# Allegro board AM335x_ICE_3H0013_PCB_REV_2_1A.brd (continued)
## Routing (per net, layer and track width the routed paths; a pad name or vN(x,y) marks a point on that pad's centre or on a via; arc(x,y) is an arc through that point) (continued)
PRUETH0_TXD2: length 45.5
  TOP w0.121: v1(60.93,74.53) 60.93,74.81 60.41,75.32 U3.5 ; v1(44.17,49.25) U14.R4 ; U37.12 59.3,60.97 v1(59.69,60.58)
  LYR3 w0.127: v1(59.69,60.58) 59.18,60.07 58.21,60.07 57.78,60.49 57.78,61.53 59.94,63.68 59.94,67.65 61.39,69.1 61.39,74.06 v1(60.93,74.53)
  BOTTOM w0.121: v1(44.17,49.25) 44.56,49.64 45.11,49.64 46.89,51.41 46.89,52.51 48.76,54.38 51.96,54.38 52.09,54.24 53.95,54.24 54.06,54.14 56.17,54.14 57.3,55.27 57.3,58.19 v1(59.69,60.58)
PRUETH0_TXD3: length 45.9
  TOP w0.121: v1(58.29,60.58) 58.29,60.96 58,61.25 U37.14 ; U3.6 v1(60.45,75.82) ; v1(44.97,49.25) U14.R3
  LYR3 w0.127: v1(58.29,60.58) 61.94,64.22 61.94,74.44 60.56,75.82 v1(60.45,75.82)
  BOTTOM w0.121: v1(44.97,49.25) 45.56,49.25 45.85,49.54 45.85,50.06 47.82,52.04 47.82,52.58 48.07,52.83 48.39,52.83 48.7,53.15 50.35,53.15 51.22,54.01 51.81,54.01 52.02,53.8 53.44,53.8 53.58,53.65 56.19,53.65 57.66,55.12 57.66,56.26 58.93,57.53 58.93,58.67 60.11,59.85 60.11,60.75 59.86,61 58.71,61 v1(58.29,60.58)
PRUETH0_TXEN: length 89.3
  TOP w0.121: v1(49.58,53.63) 49.58,52.91 48.24,51.57 48.24,51.23 46.2,49.19 45.63,49.19 45.37,48.93 U14.R2 ; v1(56.13,60.2) 56.7,60.76 U37.16 ; v1(33.77,43.65) U14.J16 ; v1(63.28,73.63) 61.32,73.63 61.05,73.36 60.56,73.36 60.1,73.82 U3.2
  LYR3 w0.127: v1(33.77,43.65) 33.34,44.08 28.41,44.08 26.47,46.02 26.47,50.5 28,52.03 29.32,52.03 31.15,53.86 31.91,53.86 31.93,53.85 v1(32.14,53.85)
  LYR4 w0.127: v1(32.14,53.85) 32.78,53.2 32.78,53.08 33.97,51.89 43.51,51.89 45.73,54.11 49.1,54.11 v1(49.58,53.63) 49.62,53.67 50.32,53.67 52.4,55.75 53.62,55.75 55.52,53.85 57.7,53.85 57.95,54.1 57.95,56.6 57.02,57.53 57.02,59.31 v1(56.13,60.2) ; v1(62.1,63.75) 62.1,64.27 61.96,64.41 61.96,64.9 63.11,66.05 63.11,70.64 63.72,71.25 63.72,73.19 v1(63.28,73.63)
  BOTTOM w0.121: v1(62.1,63.75) 60.56,62.21 57.13,62.21 TP32.1 56.13,61.21 v1(56.13,60.2)
PRUETH1_ACTLED: length 36.4
  TOP w0.121: U2.26 v1(33.31,78.32)
  LYR3 w0.127: v1(33.31,78.32) 34.29,79.3 34.29,82.93 32.58,84.64 32.58,91.32 36.36,95.09 36.36,95.11 37.57,96.32 37.57,100.82 37.85,101.09 39.67,101.09 v1(39.69,101.1)
  BOTTOM w0.121: R97.1 v1(39.69,101.1) 40.38,101.8 J1.12
PRUETH1_COL: length 23.5
  TOP w0.121: U7.1 43.42,67.32 43.18,67.56 42.75,67.56 v1(42.65,67.46) ; U2.42 38.49,69.35 R27.1 38.35,69.47 v1(37.72,69.47) ; U9.11 v1(29.98,63.25)
  LYR3 w0.127: v1(37.72,69.47) 37.72,69.15 32.8,64.23 30.97,64.23 v1(29.98,63.25)
  BOTTOM w0.121: v1(37.72,69.47) 38.35,68.83 38.35,67.45 38.36,67.45 38.36,67.36 38.79,66.93 40.54,66.93 41.07,67.46 v1(42.65,67.46)
PRUETH1_INTN: length 3
  TOP w0.121: R18.1 44.45,76.32 U2.7
PRUETH1_JTCK: length 3.1
  TOP w0.121: U2.8 45.73,76.82 TP16.1
PRUETH1_JTDI: length 6.8
  TOP w0.121: TP8.1 46.93,81.47 45.27,81.47 44.83,81.03 44.83,79.76 43.9,78.82 U2.12
PRUETH1_JTDO: length 3.3
  TOP w0.121: TP14.1 45.32,77.32 U2.9
PRUETH1_JTMS: length 3.7
  TOP w0.121: U2.10 44.42,77.82 TP12.1
PRUETH1_JTRSTN: length 4.4
  TOP w0.121: U2.11 44.03,78.32 45.21,79.5 45.21,80.01 TP10.1
PRUETH1_LINKLED: length 37.8
  TOP w0.121: U2.28 v1(33.29,77.32)
  LYR4 w0.127: TP17.1 31.24,82.26 31.65,82.67 31.65,90.27 28.83,93.09 28.83,100.58 30.05,101.8 J1.10
  BOTTOM w0.121: v1(33.29,77.32) 32.89,77.72 32.89,78.5 33.02,78.62 33.02,80.14 31.88,81.28 TP17.1 ; R95.1 v1(37.15,101.09) 36.44,101.8 J1.10
PRUETH1_RXD3: length 22.3
  TOP w0.121: U2.46 v1(40.49,70.1) 40.51,70.08 R29.1 ; U11.14 42.66,60.44 v1(42.74,60.36)
  LYR4 w0.127: v1(40.49,70.1) 40.49,71.23 40.82,71.56 41.5,71.56 41.61,71.45 41.61,70.89 41.72,70.77 41.88,70.77 41.99,70.89 41.99,71.45 42.1,71.56 42.52,71.56 43.07,71.02 43.07,69.69 43.42,69.33 43.42,69.1 43.07,68.74 43.07,66.94 42.51,66.38 42.26,66.38 41.64,65.76 41.64,64.91 42.07,64.47 42.07,63.52 42.38,63.21 42.38,62.48 42.33,62.42 42.33,61.76 42.44,61.65 43.05,61.65 43.16,61.54 43.16,61.38 43.05,61.27 42.44,61.27 42.33,61.16 42.33,60.9 42.74,60.48 v1(42.74,60.36)
PRUETH1_RXDV: length 40
  TOP w0.121: 36.98,72.48 36.98,72.51 36.42,73.08 35.86,73.08 35.27,72.49 35.27,69.78 35.03,69.53 34.54,69.53 34.4,69.67 34.4,70.84 34.26,70.98 34.06,70.98 33.92,70.84 33.92,69.67 33.78,69.53 33.57,69.53 33.43,69.67 33.43,70.84 33.29,70.98 33.09,70.98 32.95,70.84 32.95,69.67 32.81,69.53 32.61,69.53 32.47,69.67 32.47,70.84 32.33,70.98 32.13,70.98 31.99,70.84 31.99,69.67 31.84,69.53 31.18,69.53 31.17,69.54 30.83,69.54 30.48,69.19 U9.5 ; 36.98,72.48 36.99,72.48 37.08,72.57 37.08,72.9 v1(35.81,74.17) ; 36.98,72.48 U2.39
  BOTTOM w0.121: J19.2 45.57,82.78 45.57,82.4 44.03,80.85 44.03,77.66 40.45,74.08 35.94,74.08 35.86,74.17 v1(35.81,74.17) 35.69,74.04 TP36.1
PRUETH1_RXERR: length 20.4
  TOP w0.121: U7.2 42.47,66.67 42.34,66.8 v1(42.33,66.8) 41.95,66.8 41.85,66.91 41.85,67.54 41.66,67.73 41.32,67.73 41.15,67.56 41.15,66.51 40.87,66.23 40.87,65.86 41.16,65.57 U11.6 ; U2.41 v1(37.98,70.74)
  BOTTOM w0.121: v1(37.98,70.74) 37.93,70.79 37.84,70.79 37.32,70.27 37.32,69.66 37.3,69.64 37.3,69.25 37.99,68.56 37.99,67.08 38.66,66.42 40.77,66.42 41.15,66.8 v1(42.33,66.8) 44.2,66.8 R138.2
PRUETH1_RXERR_COL: length 11.8
  TOP w0.121: v1(46.44,65.35) 46.5,65.41 46.96,65.41 47.09,65.54 47.09,65.89 46.96,66.03 U7.4 ; U11.11 41.16,60.67 v1(40.79,60.3)
  LYR3 w0.127: v1(46.44,65.35) 45.89,65.35 43.24,62.7 42.6,62.7 42.33,62.42 42.33,61.84 v1(40.79,60.3)
  BOTTOM w0.121: v1(46.44,65.35) 46.44,65.58 R138.1
PRUETH1_SPEEDLED: length 50.8
  TOP w0.121: v1(31.37,54.98) 31.38,54.98 31.38,54.97 31.25,54.84 31.25,54.35 31.01,54.11 31.01,51.94 32.5,50.45 U14.U18 ; U2.27 32.74,77.82 R15.1 32,78.36 30.48,78.36 v1(30.23,78.11) 29.84,77.72 D5.1
  LYR4 w0.127: v1(31.37,54.98) 31.39,54.98 31.57,55.16 31.57,59.35 33.82,61.6 34.88,61.6 35.47,62.19 35.47,63.72 36.1,64.35 36.13,64.35 36.48,64.7 36.48,68.42 35.55,69.35 35.34,69.35 34.81,68.82 34.6,68.82 34.45,68.97 34.45,69.18 34.98,69.71 34.98,69.92 34.83,70.07 34.62,70.07 34.09,69.54 33.88,69.54 33.73,69.69 33.73,69.9 34.77,70.94 34.77,71.62 34.63,71.77 34.24,71.77 34.09,71.92 34.09,72.13 34.24,72.28 34.63,72.28 34.77,72.43 34.77,72.64 34.63,72.79 34.24,72.79 34.09,72.94 34.09,73.15 34.24,73.3 34.63,73.3 34.77,73.44 34.77,73.65 34.63,73.8 34.24,73.8 34.09,73.95 34.09,74.16 34.24,74.31 34.63,74.31 34.77,74.46 34.77,75.21 34.44,75.54 34.12,75.54 33.97,75.39 33.97,74.94 33.82,74.79 33.61,74.79 33.46,74.94 33.46,75.39 33.31,75.54 32.89,75.54 32.35,76.08 32.35,77.64 31.84,78.14 30.26,78.14 v1(30.23,78.11)
  BOTTOM w0.121: TP40.1 30.73,78.61 v1(30.23,78.11)
PRUETH1_SWSTRAP: length 2
  TOP w0.121: U2.21 v1(37.49,81.39)
  BOTTOM w0.121: R129.1 37.59,81.28 v1(37.49,81.39)
PRUETH1_TXCLK: length 10.9
  TOP w0.121: v1(44.49,72.67) 44.47,72.67 43.82,73.32 U2.1 ; v1(43.91,64.77) 43.31,64.77 U11.2
  LYR4 w0.127: v1(43.91,64.77) 44.49,65.34 44.49,68.37 44.69,68.57 44.69,69.86 44.49,70.06 v1(44.49,72.67)
PRUETH1_TXD0: length 33.9
  TOP w0.121: v1(41.82,73.67) 42.02,73.88 42.02,74.05 42.29,74.32 U2.3 ; U11.13 42.16,59.58 41.82,59.24 40.56,59.24 37.96,61.84 37.96,61.84 v1(37.95,61.86) 37.61,62.19 36.1,62.19 35.37,62.93 35.37,65.22 35.35,65.24 35.35,67.26 34.13,68.48 32.55,68.48 31.98,67.91 U9.2
  LYR3 w0.127: v1(41.82,73.67) 41.82,70.24 39.81,68.24 39.81,67.74 37.74,65.68 37.74,62.06 v1(37.95,61.86)
PRUETH1_TXEN: length 29.7
  TOP w0.121: v1(41.67,66.39) 41.66,66.38 U11.5 ; TP33.1 45.47,72.52 v1(44.16,73.82) U2.2 ; U11.3 v1(42.66,65.41)
  LYR3 w0.127: v1(44.16,73.82) 43.74,73.41 43.05,73.41 42.71,73.06 42.71,71.14 42.92,70.93 43.5,70.93 43.65,71.07 43.65,71.72 43.8,71.87 44.48,71.87 44.69,71.67 44.69,68.83 43.74,67.88 41.92,67.88 41.66,67.62 41.66,66.4 v1(41.67,66.39)
  LYR4 w0.127: v1(44.16,73.82) 43.98,73.64 43.98,69.85 44.19,69.65 44.19,68.78 43.98,68.58 43.98,66.73 v1(42.66,65.41)
PRUETH_MDC: length 52.5
  TOP w0.121: v1(31.75,76.83) 31.98,76.61 32.27,76.61 33.06,75.82 U2.31 ; U3.31 51.82,75.82 52.07,75.58 v1(52.07,75.44)
  LYR3 w0.127: v1(34.88,62.75) 35.65,61.98 36.45,61.98 37.03,61.41 38.38,61.41 38.63,61.66 38.63,65.59 38.98,65.94 41.06,65.94 41.38,65.62 42.27,65.62 42.69,66.03 44.16,66.03 46.92,68.8 47.46,68.8 49.82,71.16 49.82,72.84 52.07,75.09 v1(52.07,75.44)
  LYR4 w0.127: v1(31.75,76.83) 31.28,76.37 31.28,74.27 32.09,73.45 32.09,70.65 34.16,68.58 34.18,68.58 35.26,67.5 35.26,64.72 34.97,64.43 34.62,64.43 34.38,64.18 34.38,63.83 34.88,63.34 v1(34.88,62.75)
  BOTTOM w0.121: v1(34.88,62.75) 34.92,62.7 R148.1 R149.1 R150.1
PRUETH_MDIO: length 45.4
  TOP w0.121: U3.30 51.56,76.32 51.69,76.45 51.99,76.45 v1(52.07,76.53) ; U2.30 v1(33.28,76.32)
  LYR3 w0.127: v1(38.2,62.46) 38.2,65.56 38.84,66.2 41.27,66.2 41.5,65.97 41.84,65.97 41.85,65.98 42.27,65.98 42.69,66.39 43.79,66.39 49.31,71.92 49.31,72.85 51.29,74.83 51.29,75.75 v1(52.07,76.53)
  LYR4 w0.127: v1(38.2,62.46) 38.1,62.56 38.1,66.07 37.55,66.62 37.55,68.12 35.98,69.69 35.25,70.42 35.25,75.28 34.21,76.32 v1(33.28,76.32)
  BOTTOM w0.121: R147.1 R146.1 R145.1 38.36,61.22 38.36,62.19 38.2,62.35 v1(38.2,62.46)
PRUETHER0_RDN: length 15.6
  TOP w0.102: v1(58.02,81.9) 57.74,81.62 57.74,80.4 U3.13
  LYR3 w0.102: v1(58.02,81.9) 57.84,82.09 57.84,84.73 60.82,87.72 60.82,89.03 61.43,89.64 62.59,89.64 62.67,89.57 62.67,89.1 J2.2
  BOTTOM w0.102: R116.2 58.17,83.31 58.06,83.21 58.06,81.95 v1(58.02,81.9)
PRUETHER0_RDP: length 15.7
  TOP w0.102: v1(57.22,81.9) 57.43,81.68 57.43,80.34 U3.14
  LYR3 w0.102: v1(57.22,81.9) 57.53,82.22 57.53,84.86 60.52,87.84 60.52,89.15 61.31,89.95 62.25,89.95 J2.1
  BOTTOM w0.102: R117.2 57.66,83.31 57.76,83.21 57.76,82.45 v1(57.22,81.9)
PRUETHER0_TDN: length 14.4
  TOP w0.102: U3.16 56.26,80.38 56.26,81.7 v1(56.52,81.95)
  LYR3 w0.102: J2.6 57.5,89 57.5,89.25 57.12,89.63 56.34,89.63 55.74,89.03 55.74,87.06 56.31,86.49 56.31,82.16 v1(56.52,81.95)
  BOTTOM w0.102: v1(56.52,81.95) 56.03,82.44 56.03,83.21 56.13,83.31 R118.2
PRUETHER0_TDP: length 14.4
  TOP w0.102: U3.17 55.96,80.36 55.96,81.71 v1(55.72,81.95)
  LYR3 w0.102: v1(55.72,81.95) 56.01,82.25 56.01,86.36 55.44,86.93 55.44,89.15 56.21,89.93 57.15,89.93 J2.5
  BOTTOM w0.102: v1(55.72,81.95) 55.73,81.97 55.73,83.21 55.63,83.31 R119.2
PRUETHER1_RDN: length 14.4
  TOP w0.102: U2.13 41.46,80.3 41.46,80.31 41.45,80.31 41.45,81.28 41.58,81.4 41.58,81.85 v1(41.89,82.16)
  LYR3 w0.102: J1.2 42.35,89.1 42.35,89.41 42.23,89.53 41.01,89.53 40.5,89.03 40.5,87.52 41.63,86.39 41.63,82.42 v1(41.89,82.16)
  BOTTOM w0.102: v1(41.89,82.16) 41.68,82.37 41.68,83.08 41.78,83.19 R120.2
PRUETHER1_RDP: length 14.5
  TOP w0.102: U2.14 41.15,80.44 41.15,81.4 41.27,81.53 41.27,81.97 v1(41.09,82.16)
  LYR3 w0.102: J1.1 41.82,89.84 40.88,89.84 40.2,89.15 40.2,87.39 41.32,86.27 41.32,82.39 v1(41.09,82.16)
  BOTTOM w0.102: R121.2 41.27,83.19 41.38,83.08 41.38,82.45 v1(41.09,82.16)
PRUETHER1_TDN: length 16.5
  TOP w0.102: U2.16 39.88,80.38 39.88,81.95 v1(40.14,82.21)
  LYR3 w0.102: v1(40.14,82.21) 39.89,82.46 39.89,84.76 38.11,86.54 36.51,86.54 35.42,87.63 35.42,89.03 35.97,89.58 36.85,89.58 37.09,89.33 37.09,88.92 J1.6
  BOTTOM w0.102: R122.2 39.75,83.19 39.65,83.08 39.65,82.7 v1(40.14,82.21)
PRUETHER1_TDP: length 16.6
  TOP w0.102: v1(39.33,82.21) 39.57,81.97 39.57,80.36 U2.17
  LYR3 w0.102: v1(39.33,82.21) 39.58,82.46 39.58,84.64 37.98,86.23 36.39,86.23 35.12,87.5 35.12,89.15 35.84,89.88 36.78,89.88 J1.5
  BOTTOM w0.102: R123.2 39.24,83.19 39.34,83.08 39.34,82.22 v1(39.33,82.21)
PWR_SWIO: length 1.3
  TOP w0.254: U22.14 13.69,11.45 13.46,11.68
PWR_VAUX1: length 11.3
  TOP w0.203: U22.46 21.34,11.05 21.36,11.07 21.39,11.07 22.03,11.72 22.03,17.21
  TOP w0.254: v2(23.62,18.8) 22.03,17.21
  TOP w0.508: C53.1 v2(23.62,18.8)
  BOTTOM w0.508: v2(23.62,18.8) 23.36,18.53 R214.1
PWR_VAUX2: length 10.6
  TOP w0.203: U22.48 20.63,12.37 v2(20.7,12.45)
  LYR4 w0.508: v2(24.64,17.53) 23.14,16.03 23.14,14.5 21.08,12.45 v2(20.7,12.45)
  BOTTOM w0.508: C237.1 25.91,18.92 25.52,18.53 R213.1 v2(24.64,17.53)
PWR_VAUX33: length 16.6
  TOP w0.203: 18.81,18.05 18.81,16.99 18.73,16.92 18.73,13.97 18.65,13.89 U22.4
  TOP w0.254: v2(19.56,18.8) 18.81,18.05
  TOP w0.508: v2(14.22,17.27) 13.96,17.54 R78.1 ; C51.1 v2(19.56,18.8)
  LYR4 w0.508: v2(19.56,18.8) 18.54,17.78 18.54,17.27 17.91,16.64 14.86,16.64 v2(14.22,17.27)
  BOTTOM w0.508: v2(19.56,18.8) 19.29,18.53 R216.2
PWR_VDAC: length 11.8
  TOP w0.203: U22.22 13.97,8.25 13.84,8.38 v2(13.59,8.38)
  TOP w0.508: v2(11.53,14.74) 11.53,15.63 R77.1
  LYR4 w0.508: v2(13.59,8.38) 13.08,8.38 11.43,10.03 11.43,14.64 v2(11.53,14.74)
  BOTTOM w0.508: v2(11.53,14.74) 11.53,16.66 C244.1
PWR_VDD1_SMPS: length 1.6
  TOP w0.203: U22.32 18.25,5.5 18.54,5.21
PWR_VDD2_SMPS: length 1.5
  TOP w0.203: 21.97,10.54 21.68,10.25 U22.44
PWR_VDDIO: length 4.4
  TOP w0.203: U22.12 15.45,12.73 15.09,12.73
  TOP w0.381: R78.2 12.95,14.86 15.09,12.73
PWR_VDDS_DDR: length 1.1
  TOP w0.254: U22.16 13.7,10.65 13.59,10.54
PWR_VDIG1: length 8.9
  TOP w0.203: 16.7,17.14 16.7,14.03 17.45,13.28 U22.7
  TOP w0.254: v2(15.49,18.8) 16.7,17.59 16.7,17.14
  TOP w0.508: C49.1 v2(15.49,18.8)
  BOTTOM w0.508: v2(15.49,18.8) 15.23,18.53 R218.2
PWR_VDIG2: length 8.4
  TOP w0.203: U22.5 18.25,14.06 18.35,14.16 18.35,17.36
  TOP w0.254: 18.35,17.36 18.35,17.78 17.53,18.61 v2(17.53,18.8)
  TOP w0.508: C50.1 v2(17.53,18.8)
  BOTTOM w0.508: R217.2 17.26,18.53 v2(17.53,18.8)
PWR_VMMC: length 9.3
  TOP w0.203: U22.2 19.45,13.23 19.63,13.41 20.01,13.41 20.38,13.79 20.38,17.14
  TOP w0.254: 20.38,17.14 20.38,17.8 20.89,18.31 21.11,18.31 v2(21.59,18.8)
  TOP w0.508: C52.1 v2(21.59,18.8)
  BOTTOM w0.508: v2(21.59,18.8) 21.33,18.53 R215.2
PWR_VPLL: length 14.3
  TOP w0.254: v2(13.59,6.86) 14.35,6.86 14.58,7.09 14.58,7.35 U22.24
  TOP w0.508: v2(9.91,14.73) R76.1
  LYR4 w0.508: v2(9.91,14.73) 9.91,9.91 12.83,6.99 13.22,6.99 13.35,6.86 v2(13.59,6.86)
  BOTTOM w0.508: v2(9.91,14.73) C245.1
PWRON: length 4.6
  TOP w0.203: U22.33 18.65,5.86 v1(18.92,5.59)
  TOP w0.381: TP30.1 20.83,3.81 v1(20.08,3.81)
  LYR3 w0.508: v1(18.92,5.59) 18.95,5.59 20.06,4.48 20.06,3.83 v1(20.08,3.81)
RESN: length 4.6
  BOTTOM w0.121: R230.2 61.08,5.46 61.08,5.14 60.7,4.75 59.24,4.75 58.56,4.08 J17.6
RTC_PORZ: length 30.4
  TOP w0.121: v1(42.57,38.05) U14.B5 ; U13.7 24.14,46.73 v1(24.26,46.61)
  LYR3 w0.127: v1(42.57,38.05) 42.57,38.29 42.17,38.69 42.17,39.81 41.93,40.04 40.76,40.04 40.46,40.35 39.88,40.35 39.58,40.04 33.61,40.04 31.4,37.83 28.97,37.83 27.01,39.79 27.01,40.08 24.3,42.8 24.3,46.57 v1(24.26,46.61)
  BOTTOM w0.121: R176.2 23.88,46.99 v1(24.26,46.61)
RTCK: length 3.7
  TOP w0.121: R22.1 v1(72.8,69.55)
  BOTTOM w0.121: v1(72.8,69.55) J15.9
SENSE: length 4
  TOP w0.635: R66.2 R67.1 46.23,22.73 46.74,22.23 U21.4
SPI0_CS0: length 17
  TOP w0.121: U17.1 33.27,27.94 33.75,27.47 33.75,27.09 34.06,26.77 36.17,26.77 36.58,27.18 36.58,29.34 36.4,29.51 35.58,29.51 34.69,30.4 34.69,31.21 34.29,31.61 34.29,33.15 34.1,33.35 34.1,33.49 33.95,33.63 33.95,35.87 34.17,36.09 U14.A16
SPI0_CS1: length 45.6
  TOP w0.121: v1(34.75,29.08) 34.75,29.99 34.22,30.52 34.06,30.52 33.78,30.8 33.78,30.87 33.67,30.98 31.74,30.98 31.25,31.48 31.25,32.76 31.86,33.37 31.86,34.73 v1(33.57,36.43) ; v1(34.57,38.85) U14.C15
  LYR3 w0.127: v1(34.57,38.85) 34.57,38.63 34.07,38.13 34.07,37.37 33.57,36.87 33.57,36.44 v1(33.57,36.43)
  LYR4 w0.127: v1(34.75,29.08) 35.18,29.51 36.08,29.51 36.09,29.5 43.42,29.5 43.94,28.98 50.5,28.98 53.65,25.84 53.65,22.89 54.61,21.92 54.61,20.87 56.73,18.75 57.07,18.75 v1(57.53,18.29)
  BOTTOM w0.121: U35.24 57.89,17.93 v1(57.53,18.29)
SPI0_D0: length 58.6
  TOP w0.121: TP39.1 50.97,16.34 50.97,17.95 50.29,18.63 R75.1 v1(50.29,19.43) 50.66,19.8 U20.4 ; v1(37.08,26.28) 32.64,26.28 31.37,27.55 31.37,28.71 31.62,28.96 32.32,28.96 U17.2 30.1,29.21 29.46,28.57 28.48,28.57 28.04,29.01 27.24,29.01 26.94,28.71 24.75,28.71 24.64,28.82 24.64,29.89 24.14,30.39 24.14,32.35 24.54,32.76 27.16,32.76 27.32,32.6 28.88,32.6 30.66,34.38 30.66,34.8 32.97,37.11 32.97,38.05 U14.B17
  LYR4 w0.127: v1(50.29,19.43) 49.7,19.43 46.65,22.48 46.65,24.34 47.5,25.19 47.5,25.93 46.35,27.08 43.85,27.08 43.42,26.66 40.2,26.66 39.82,26.28 39.81,26.28 v1(37.08,26.28)
SPI0_D1: length 18.3
  TOP w0.121: U17.5 26.75,31.75 27.25,31.25 28.39,31.25 29.42,30.22 v1(29.79,30.22) 29.84,30.22 30.04,30.41 30.28,30.41 30.85,30.98 30.85,33.15 31.62,33.91 31.62,35.11 33.77,37.26 33.77,38.05 U14.B16
  BOTTOM w0.121: v1(29.79,30.22) 28.6,30.22 28.16,29.78 28.16,29.2 28.83,28.53 TP38.1
SPI0_SCLK: length 62.2
  TOP w0.121: U14.A17 33.37,37.18 31.08,34.88 31.08,34.08 30.35,33.36 30.35,32.65 29.45,31.75 27.46,31.75 26.95,32.25 24.75,32.25 24.64,32.14 24.64,30.98 25.15,30.48 U17.6 27.81,30.48 28.44,29.85 28.44,29.32 28.68,29.07 29.16,29.07 29.8,29.71 33.67,29.71 34.08,29.31 34.08,28.13 34.35,27.85 34.88,27.85 34.88,27.87 35.03,28.01 35.03,28.22 v1(35.81,29.01)
  LYR4 w0.127: v1(58.22,19.41) 58.04,19.23 58.04,18.08 57.74,17.78 56.5,17.78 56.44,17.84 53.89,20.4 53.89,21.45 53.14,22.2 53.14,25.63 50.29,28.48 43.73,28.48 43.36,28.85 41.37,28.85 41.12,28.6 40.84,28.32 36.5,28.32 v1(35.81,29.01)
  BOTTOM w0.121: v1(58.22,19.41) 58.54,19.09 U35.25
SPI1_CS0: length 92.1
  TOP w0.121: v1(36.97,38.85) U14.C12
  LYR3 w0.127: v1(11.76,39.65) 13.49,37.92 13.49,37.74 17.24,33.99 20.68,33.99 21.72,32.94 29.87,32.94 32.18,35.26 34.66,35.26 35.2,35.8 35.2,37.17 35.78,37.74 35.78,38.21 36.01,38.45 36.34,38.45 36.74,38.85 v1(36.97,38.85)
  LYR4 w0.127: v1(11.76,39.65) 12.18,40.07 12.42,40.07 12.66,40.31 12.66,55.71 11.34,57.04 11.34,62.65 8.58,65.41 8.58,89.54 5.89,92.23 4.04,92.23 J3.18
SPI1_D0: length 87.3
  TOP w0.121: v1(36.17,38.05) U14.B13
  LYR3 w0.127: v1(11.18,40.53) 11.18,38.65 14.05,35.77 14.05,35.65 15.97,33.73 18.68,33.73 20.93,31.48 29.87,31.48 31.56,33.17 32.92,33.17 34.14,34.39 34.65,34.39 35.66,35.41 35.66,36.83 36.17,37.34 v1(36.17,38.05)
  LYR4 w0.127: J3.14 3.94,87.25 5.79,87.25 7.51,85.53 7.51,65.27 9.64,63.15 9.64,57.18 11.18,55.64 v1(11.18,40.53)
SPI1_D1: length 87.7
  TOP w0.121: v1(36.97,39.65) U14.D12
  LYR3 w0.127: v1(36.97,39.65) 36.74,39.65 36.33,39.25 36.01,39.25 35.77,39.01 35.77,38.69 35.53,38.45 35.21,38.45 34.98,38.21 34.98,36.45 34.24,35.71 31.79,35.71 30.33,34.25 17.99,34.25 16.46,35.78 16.46,36.53 14.81,38.18 14.55,38.18 v1(12.24,40.49)
  LYR4 w0.127: J3.16 3.86,89.87 5.72,89.87 8.03,87.55 8.03,65.37 10.13,63.26 10.13,57.47 12.24,55.36 v1(12.24,40.49)
SPI1_SCLK: length 87.1
  TOP w0.121: v1(35.43,32.38) 35.43,32.76 35.57,32.9 35.57,36.65 U14.A13
  LYR3 w0.127: v1(10.16,39.62) 10.16,38.95 13.46,35.65 13.46,35.22 16.34,32.35 17.61,32.35 18.37,31.58 18.54,31.58 20.48,29.64 21.39,29.64 22.14,30.39 28.66,30.39 29.25,29.8 29.27,29.79 29.29,29.79 29.96,29.79 30.08,29.91 31.73,29.91 34.2,32.38 v1(35.43,32.38)
  LYR4 w0.127: J3.12 4.06,84.58 4.06,71.59 5.44,70.21 5.44,65.36 8.71,62.08 8.71,56.42 9.76,55.37 9.76,41.45 10.16,41.05 v1(10.16,39.62)
SYS_BOOT0: length 15
  TOP w0.121: 62.48,65.15 v1(62.48,64.48) ; U37.2 v1(54.75,58.67)
  BOTTOM w0.121: 62.48,65.15 v1(62.48,64.48) 62.67,64.29 62.67,63.45 62.7,63.42 62.7,62.93 61.62,61.85 57.92,61.85 56.55,60.48 56.55,60.03 56.31,59.78 55.86,59.78 v1(54.75,58.67)
SYS_BOOT1: length 11.7
  TOP w0.121: U37.4 v1(56.05,58.67)
  BOTTOM w0.121: J5.2 62.46,61.49 58.1,61.49 57.51,60.9 57.51,60.14 v1(56.05,58.67)
SYS_BOOT2: length 11.5
  TOP w0.121: U37.6 57.35,57.98 58.04,58.67 59.11,58.67 60.85,60.41 60.85,63.99 v1(60.45,64.39) 60.45,65.15
  BOTTOM w0.121: 60.45,65.15 v1(60.45,64.39)
SYS_BOOT3: length 10.4
  TOP w0.121: 61.47,65.15 v1(61.47,64.39) 61.21,64.14 61.21,60.26 58.65,57.7 U37.8
  BOTTOM w0.121: 61.47,65.15 v1(61.47,64.39)
SYS_BOOT4: length 3.6
  TOP w0.121: 59.44,65.15 v1(59.44,64.48) 59.95,63.97 U37.11
  BOTTOM w0.121: 59.44,65.15 v1(59.44,64.48)
SYS_BOOT5: length 3.5
  TOP w0.121: 58.42,65.15 v1(58.42,64.48) 58.65,64.25 U37.13
  BOTTOM w0.121: 58.42,65.15 v1(58.42,64.48)
SYS_BOOT6: length 3.4
  TOP w0.121: U37.15 57.35,64.42 v1(57.4,64.48) 57.4,65.15
  BOTTOM w0.121: 57.4,65.15 v1(57.4,64.48)
SYS_BOOT7: length 3.5
  TOP w0.121: U37.17 56.05,64.14 v1(56.39,64.48) 56.39,65.15
  BOTTOM w0.121: 56.39,65.15 v1(56.39,64.48)
SYS_BOOT8: length 3.7
  TOP w0.121: 48.26,65.15 v1(48.26,64.39)
  BOTTOM w0.121: 48.26,65.15 v1(48.26,64.39) 47.64,63.76 U38.2
SYS_BOOT9: length 3.6
  TOP w0.121: 49.28,65.15 v1(49.28,64.39)
  BOTTOM w0.121: 49.28,65.15 v1(49.28,64.39) 49.28,63.71 48.94,63.37 U38.4
SYS_BOOT10: length 3.5
  TOP w0.121: v1(50.33,64.44) 50.29,64.48 50.29,65.15
  BOTTOM w0.121: 50.29,65.15 50.29,64.48 v1(50.33,64.44) 50.33,62.56 U38.6
SYS_BOOT11: length 3.8
  TOP w0.121: v1(51.12,64.39) 51.31,64.58 51.31,65.15
  BOTTOM w0.121: U38.8 51.54,63.42 51.12,63.83 v1(51.12,64.39) 51.31,64.58 51.31,65.15
SYS_BOOT12: length 10.3
  TOP w0.121: 55.37,65.15 v1(55.37,64.39)
  BOTTOM w0.121: 55.37,65.15 v1(55.37,64.39) 55.37,63.88 54.93,63.44 54.93,60.81 52.84,58.72 U38.11
SYS_BOOT13: length 11
  TOP w0.121: v1(51.54,57.91) 51.54,58.29 50.29,59.54 50.29,62.95 51.31,63.97 51.31,63.99 51.68,64.36 51.72,64.36 51.75,64.39 52.32,64.39 v1(52.32,64.39) 52.32,65.15
  BOTTOM w0.121: U38.13 v1(51.54,57.91) ; 52.32,65.15 v1(52.32,64.39)
SYS_BOOT14: length 15.2
  TOP w0.121: 54.36,65.15 v1(54.36,64.39)
  BOTTOM w0.121: 54.36,65.15 v1(54.36,64.39) 54.56,64.18 54.56,60.96 52.52,58.91 49.67,58.91 49.4,59.18 48.99,59.18 48.73,58.93 48.73,58.37 49.2,57.91 49.91,57.91 50.24,57.59 U38.15
SYS_BOOT15: length 14.4
  TOP w0.121: 53.34,65.15 v1(53.34,64.39)
  BOTTOM w0.121: 53.34,65.15 v1(53.34,64.39) 53.55,64.18 53.55,60.46 52.37,59.27 49.91,59.27 49.62,59.56 48.77,59.56 48.13,58.93 48.13,58.46 48.94,57.66 U38.17
SYS_RESETN: length 201.1
  TOP w0.121: v1(48.39,73.41) 48.39,72.45 U5.2 ; U14.A10 38.97,37.32 37.5,35.85 37.5,35.09 36.32,33.9 36.32,33.31 36.71,32.92 36.71,30.55 36.32,30.16 v1(36.32,30.18) ; R20.2 72.48,70.82 v1(71.64,69.98)
  LYR3 w0.127: v1(53.72,33.5) 53.7,33.5 52.86,32.66 52.86,32.05 53.26,31.65 57.28,31.65 57.48,31.85 58.4,31.85 58.65,32.09 60.57,32.09 61.72,33.25 63.23,33.25 66.49,36.51 66.49,36.81 67.93,38.26 67.93,45.36 68.42,45.84 68.42,49.69 66.22,51.89 65.44,51.89 63.5,53.83 63.5,55.95 64,56.45 64.61,56.45 68.71,60.55 68.71,67.05 v1(71.64,69.98) 68.02,73.59 v1(64.04,73.59) ; v1(21.97,91.06) 22.26,90.77 24.76,90.77 31.81,83.71 31.81,82.46 32.35,81.92 32.35,76.65 33.94,75.06 40.88,75.06 41.22,74.72 47.28,74.72 48.39,73.62 v1(48.39,73.41) ; v1(36.32,30.18) 38.01,28.49 38.43,28.49 39.37,27.55 42.61,27.55 44.75,25.4 v1(46.99,25.4)
  LYR4 w0.127: v1(48.39,73.41) 48.56,73.41 50.17,75.02 58.71,75.02 60.39,73.34 61.9,73.34 62.39,73.82 62.88,73.82 63.1,74.05 63.58,74.05 v1(64.04,73.59) ; v1(46.99,25.4) 46.14,24.55 46.14,18.88 54.46,10.57 54.46,8.03 55.5,6.99 60.58,6.99 v1(61.72,8.13)
  BOTTOM w0.121: R198.2 R197.1 36.32,29.47 v1(36.32,30.18) ; R142.1 62.73,70.48 62.72,70.5 62.45,70.5 61.42,71.53 61.42,72.98 62.11,73.67 62.73,73.67 63.1,74.05 63.45,74.05 63.82,73.67 63.96,73.67 v1(64.04,73.59) ; v1(21.97,91.06) 21.34,90.42 R105.1 ; v1(53.72,33.5) 53.72,33.47 53.69,33.47 52.66,32.44 52.66,30.78 51.08,29.21 51.08,25.85 50.86,25.63 48.1,25.63 48.02,25.55 47.14,25.55 v1(46.99,25.4) ; R230.1 v1(61.72,8.13)
SYS_WARMRESETN: length 39.1
  TOP w0.121: S1.2 4.01,20.14 4.32,20.45 v1(4.32,20.83) 4.32,21.34 5.84,22.86 10.67,22.86 v1(11.43,22.1)
  LYR3 w0.127: v1(11.43,22.1) 12.45,23.11 16.36,23.11 17.16,23.91 21.09,23.91 22.34,25.16 26.97,25.16 28.85,27.04 30.75,27.04 31.04,26.76 34.81,26.76 35.3,27.24 v1(35.3,27.69)
  BOTTOM w0.121: v1(35.3,27.69) 35.3,27.69 35.22,27.78 35.22,28.36 R198.1 ; C235.1 v1(4.32,20.83)
TCK: length 3.7
  TOP w0.121: R23.1 v1(72.8,68.28)
  BOTTOM w0.121: J15.11 v1(72.8,68.28)
TDIS: length 5.1
  TOP w0.121: v1(71.85,73.36) R17.2
  BOTTOM w0.121: J15.4 v1(71.85,73.36)
TEMP_SENSE: length 13.4
  TOP w0.121: U14.B6 41.83,38.11 41.83,37.34 42.11,37.06 42.11,34.98 42.17,34.92 42.18,34.92 42.55,34.55 42.55,32.6 42.76,32.4 42.76,29.31 42.16,28.71 42.16,27.88 41.66,27.38 40.99,27.38 40.78,27.59 U19.3
TESTOUT: length 10.6
  TOP w0.121: TP24.1 48.01,32.46 44.57,35.89 U14.A3
UART0_RXD: length 33.5
  TOP w0.121: v1(34.57,40.45) U14.E15
  LYR4 w0.127: v1(17.72,43.87) 17.72,47.65 20.81,50.75 23.57,50.75 24.63,51.81 27.28,51.81 28,51.09 28.39,51.09 28.66,51.36 30.2,51.36 32.53,49.03 32.53,43.16 33.36,42.33 33.36,41.1 33.61,40.86 34.16,40.86 v1(34.57,40.45)
  BOTTOM w0.121: R181.1 17.64,43.94 v1(17.72,43.87)
UART0_TXD: length 22.6
  TOP w0.121: v1(33.77,40.45) U14.E16
  BOTTOM w0.121: R186.1 C184.1 17.66,38.73 19.74,36.65 24.71,36.65 25.87,37.81 26.24,37.81 26.79,38.35 28.53,38.35 29.05,37.84 29.37,37.84 29.6,38.07 29.6,38.37 29.96,38.73 29.96,40.08 30.36,40.48 33.73,40.48 v1(33.77,40.45)
UART1_RXD: length 34.4
  TOP w0.121: v1(33.77,39.65) U14.D16
  LYR4 w0.127: v1(24.66,50.25) 24.66,50.38 25.06,50.79 26.86,50.79 27.61,50.04 29.99,50.04 30.18,49.86 30.63,49.86 32.05,48.44 32.05,42.96 32.91,42.1 32.91,40.43 33.69,39.65 v1(33.77,39.65)
  BOTTOM w0.121: v1(24.66,50.25) 24.32,49.91 19.28,49.91 17.7,48.33 12.68,48.33 12.06,48.94 U28.5
UART1_TXD: length 43.2
  TOP w0.121: v1(34.57,39.65) U14.D15
  LYR4 w0.127: v1(34.57,39.65) 34.18,40.04 33.62,40.04 33.13,40.53 33.13,42.2 32.28,43.05 32.28,48.53 30.86,49.95 30.86,49.96 30.7,50.11 30.28,50.11 29.82,50.57 27.8,50.57 27.07,51.3 24.84,51.3 v1(23.93,50.39)
  BOTTOM w0.121: 8.26,50.93 8.26,49.78 8.51,49.53 9.91,49.53 10.16,49.78 10.16,52.7 11.74,54.29 16.51,54.29 18.68,52.11 18.68,51.5 19.79,50.39 v1(23.93,50.39)
UART3_RXD: length 33.2
  TOP w0.121: U18.38 23.62,27.71 23.79,27.87 v1(23.8,27.87) ; v1(28.66,45.57) 28.82,45.42 29.41,45.42 29.52,45.31 33.03,45.31 U14.L17
  LYR4 w0.127: v1(28.66,45.57) 27.46,45.57 25.72,47.31 23.33,47.31 22.92,46.9 22.92,43.78 23.46,43.25 23.46,42 22.99,41.53 22.99,40.32 22.31,39.65 22.31,36.15 23.38,35.09 23.38,28.27 23.78,27.87 v1(23.8,27.87)
UART3_TXD: length 33.5
  TOP w0.121: U14.L16 33.83,45.99 32.05,45.99 32.03,45.96 30.28,45.96 29.83,46.42 29.58,46.42 29.41,46.59 28.81,46.59 v1(28.77,46.63) ; U18.39 21.65,28.21 21.4,28.46 21.39,28.46 v1(21.41,28.46)
  LYR4 w0.127: v1(21.41,28.46) 21.41,28.48 21.96,29.03 21.96,33.05 21.81,33.2 21.81,39.86 22.42,40.47 22.42,47.11 23.12,47.82 25.94,47.82 26.57,47.18 28.22,47.18 v1(28.77,46.63)
UART4_RXD_SYNC0_OUT: length 66.9
  TOP w0.121: U14.E18 32.51,40.85 30.51,38.85 30.32,38.85 29.85,38.39 29.85,37.75 29.57,37.46 29.57,37.14 v1(29.54,37.12)
  LYR3 w0.127: J3.7 3.61,79.69 3.61,71.15 4.53,70.23 4.53,66.08 9.26,61.35 9.26,58.58 15.06,52.78 15.06,41.2 19.61,36.65 29.08,36.65 v1(29.54,37.12)
UART4_TXD_SYNC1_OUT: length 71.3
  TOP w0.121: U14.E17 33.03,40.51 33.03,40.03 32.62,39.62 32.46,39.62 31.12,38.28 31.12,37.44 v1(30.55,36.86)
  LYR3 w0.127: v1(30.55,36.86) 30.09,36.41 29.24,36.41 27.92,35.09 19.05,35.09 12.6,41.55 12.6,53.67 3.34,62.93 3.34,65.88 1.37,67.85 1.37,79.98 J3.8
USB_DC: length 35.6
  LYR3 w0.508: v1(13.79,27.46) 13.01,26.68 9.84,26.68 8.05,24.89 8.05,21.79 7.71,21.44 7.71,18.61 8.05,18.26 8.05,12.58 4.63,9.15 4.63,5.88 v1(5.05,5.46)
  BOTTOM w0.381: v1(13.79,27.46) 16.36,27.46 17.02,28.12 17.02,32.15
USBDM: length 5.6
  TOP w0.13: L6.3 3.89,8.17 4.19,7.87 4.19,7.3 U23.2 4.06,6.86 4.2,6.72 5.34,6.72 5.7,6.36 J13.2
USBDM_FT: length 25.5
  TOP w0.13: v1(3.93,11.42) 4.18,11.18 4.18,10.72 3.89,10.44 L6.2 ; U18.7 v1(10.17,29.71)
  LYR3 w0.13: v1(10.17,29.71) 9.01,29.71 6.06,26.75 6.06,18.48 6.74,17.79 6.74,13.75 5.78,12.79 4.48,12.79 3.93,12.25 v1(3.93,11.42)
USBDP: length 5.6
  TOP w0.13: L6.4 4.74,8.12 4.5,7.87 4.5,7.24 U23.1 4.7,7.03 5.47,7.03 6,6.49 6,5.24 6.1,5.14 6.33,5.14 6.44,5.03 6.44,4.28 J13.3
USBDP_FT: length 25.5
  TOP w0.13: L6.1 4.74,10.44 4.48,10.7 4.48,11.2 v1(4.71,11.42) ; v1(10.16,28.96) 10.41,29.21 U18.8
  LYR3 w0.13: v1(4.71,11.42) 4.24,11.89 4.24,12.12 4.61,12.49 5.91,12.49 7.04,13.63 7.04,17.92 6.36,18.6 6.36,26.62 9.14,29.4 9.8,29.4 9.93,29.27 9.93,29.19 v1(10.16,28.96)
VADD33_PRUETH0: length 6
  TOP w0.381: 52.96,83.31 v2(52.96,84.04) ; 52.96,83.31 C5.1 C2.1 ; 52.96,83.31 52.96,82.2 53.37,81.79 U3.22
  vias: v2(52.9,84.79)
VADD33_PRUETH1: length 7.2
  TOP w0.305: R7.1 36.58,81.99 36.58,81.99 36.58,81.66 36.98,81.25 U2.22
  TOP w0.381: R7.1 C3.1 C1.1 v2(35.56,85.09)
  BOTTOM w0.381: R240.1 33.03,82.66 v2(33.08,82.61)
VAUX1: length 108.1
  TOP w0.305: v2(67.18,57.02) 67.16,57.05 61.87,57.05 v2(61.47,56.64) ; v1(33.77,49.25) U14.R16 ; v1(33.77,47.65) U14.N16
  TOP w0.381: v2(67.18,57.02) C21.1 67.58,58.18 U12.3 ; R39.2 v2(66.17,59.94)
  LYR3 w0.305: 49.53,54.29 49.85,54.29 51.74,52.4 58.12,52.4 59.41,53.7 59.41,54.84 59.47,54.91 59.47,55.65 59.82,56 60.96,56 61.47,56.52 v2(61.47,56.64)
  LYR3 w0.381: 49.53,54.29 v1(43.49,54.29)
  LYR3 w0.508: v2(35.56,22.5) 35.5,22.56 v2(34.84,22.56) 34.85,22.57 34.85,23.62 34.44,24.03 30.02,24.03 29.47,23.48 28.76,23.48 28.72,23.52 22.76,23.52 v2(22.4,23.16) 22.09,22.85 v2(22.09,21.89)
  LYR4 w0.305: v2(67.18,57.02) 67.18,58.93 v2(66.17,59.94)
  LYR4 w0.381: 29.88,48.61 v2(29.92,48.61)
  LYR4 w0.508: v2(29.41,49.07) 29.88,48.61 ; v1(33.77,47.65) 33.66,47.76 33.66,49.14 v1(33.77,49.25) ; v2(29.92,48.61) 30.01,48.51 30.62,48.51 31.19,47.94 31.19,42.52 31.88,41.84 31.88,39.44 32.84,38.48 32.93,38.39 32.93,35.97 33.51,35.38 33.51,33.47 32.91,32.87 32.91,25.6 34.84,23.67 v2(34.84,22.56)
  BOTTOM w0.305: C124.1 32.91,48.51 v1(33.77,47.65) 33.17,47.05 32.71,47.05 C132.1
  BOTTOM w0.381: v1(43.49,54.29) 43.1,54.29 42.76,54.62 42.18,54.62 41.14,53.58 39.9,53.58 39.61,53.86 38.06,53.86 35.95,53.86 34.8,52.7 34.19,52.7 33.12,51.64 ; 33.12,51.64 32.89,51.41 32.89,50.04 33.68,49.25 v1(33.77,49.25) ; 33.12,51.64 32.92,51.64 32.35,52.21 31.39,52.21 29.46,50.29 29.46,49.12 ; v2(29.41,49.07) 29.46,49.12 ; 29.46,49.12 29.46,49.06 v2(29.92,48.61)
VAUX2: length 88.4
  TOP w0.254: U14.E10 38.71,40.59 38.43,40.59 U14.E11
  TOP w0.305: U14.G14 v1(35.37,42.05) U14.F14 ; U14.E11 v1(37.77,40.45) U14.E12 v1(36.97,40.45) U14.E13 ; U14.P5 v1(42.57,48.45) U14.P6 ; U14.P5 42.57,47.65 ; U14.P5 v1(43.37,48.45) ; 42.57,47.65 U14.N5 ; 42.57,47.65 U14.P6 ; U14.P13 v1(36.17,48.45) ; U14.K14 v1(35.37,45.25) U14.L14 ; U14.P12 v1(36.97,48.45) ; U14.P8 v1(40.97,48.45) U14.P7 v1(41.77,48.45) U14.P6
  TOP w0.381: R46.2 R43.2 R44.2 ; R46.2 52.32,66.8 v2(52.2,66.93) ; R46.2 R45.2 R47.2 ; R56.2 R55.2 R57.2 v2(62.48,66.93) ; R56.2 v2(60.45,66.93) ; R56.2 R54.2 R53.2 ; v2(62.23,63.12) 61.98,62.87 R37.2 ; R70.2 R71.2 v1(13.46,21.34) ; R53.2 v2(58.42,66.93) ; R53.2 R52.2 R51.2 ; R44.2 54.36,66.67 v2(54.61,66.93) ; R44.2 R48.2 R51.2 ; R47.2 v2(50.29,66.93) ; R47.2 R49.2 R50.2 v2(48.26,66.93) ; R51.2 v2(56.39,66.93) ; v2(64.39,66.93) C23.1 v2(65.9,65.64)
  LYR4 w0.254: v1(35.86,27.28) 36.01,27.13
  LYR4 w0.508: v2(62.89,21.72) v2(62.89,21.03) 62.24,20.38 60.48,20.38 60.36,20.5 59.63,20.5 59.11,19.98 59.11,19.23 59.76,18.58 59.76,18.06 58.78,17.08 53.94,17.08 51.7,19.32 51.71,19.33 51.71,19.87 51.33,20.26 50.78,20.26 50.77,20.25 50.29,20.73 50.29,24.13 46.64,27.78 43.56,27.78 43.14,27.36 42.83,27.36 40.97,27.36 40.79,27.53 37.09,27.53 36.69,27.13 36.01,27.13
  BOTTOM w0.305: v1(41.77,48.45) v1(40.97,48.45) ; v1(35.37,45.25) 35.37,45.94 C139.1 ; C173.2 35.37,41.36 v1(35.37,42.05)
  BOTTOM w0.381: C172.2 38.65,40.45 v1(37.77,40.45) ; v1(36.2,36.32) 36.83,36.32 37.21,35.94 C202.2 C201.1 ; R197.2 36.32,28.15 v1(36.02,27.84) ; R196.2 32.77,29.97 33.78,30.99 34.04,30.99 34.07,31.02 v2(34.22,31.02)
  BOTTOM w0.508: v2(24.64,21.34) R213.2
  vias: v1(24.62,21.97) v1(29.98,35.32) v1(29.95,34.76)
VAUX33: length 128.1
  TOP w0.305: v1(34.57,49.25) U14.R15 ; v1(34.57,47.65) U14.N15
  TOP w0.508: v2(69.9,36.57) 69.9,34.24 R63.2
  LYR3 w0.381: v2(30.35,47.88) 30.35,47.32 v2(30.46,47.21) ; 33.43,49.94 33.88,49.94 v1(34.57,49.25)
  LYR3 w0.508: v2(68.83,26.54) v2(68.07,26.54) 67.77,26.54 65.07,23.84 65.07,21.94 60.72,17.59 58.9,17.59 58.87,17.61 58.86,17.61 58.45,18.02 58.45,18.04 58.17,18.32 58.17,18.52 56.43,20.26 54.83,20.26 54.08,21.01 54.08,21.21 53.72,21.56 53.21,21.56 53.05,21.4 43.57,21.4 41.49,23.48 39.88,23.48 38.07,21.67 34.35,21.67 33.86,22.17 33.86,22.68 33.58,22.96 v2(30.79,22.96) v1(30.26,22.42) 30.1,22.58 23.98,22.58 22.98,21.58 22.98,21.41 22.24,20.68 19.2,20.68 v2(18.54,21.34) 18.29,21.59 v2(17.88,21.59) ; 33.43,49.94 32.92,49.94 31.11,48.13 30.61,48.13 v2(30.35,47.88)
  LYR4 w0.508: v2(30.35,47.88) 30.46,47.77 v2(30.46,47.21) 29.9,46.65 29.9,42.71 29.92,42.69 29.92,42.68 30.26,42.34 30.27,42.34 31.13,41.48 31.13,34.95 30.12,33.95 30.12,31.3 30.14,31.28 30.3,31.08 30.53,30.86 30.53,30.1 30.79,29.84 v2(30.79,22.96) v1(30.26,22.42) ; v1(34.57,49.25) 34.42,49.1 34.42,47.8 v1(34.57,47.65)
  BOTTOM w0.305: C186.1 71.08,38.73 71.08,41.7 70.61,42.16 R184.2
  BOTTOM w0.381: v1(34.57,47.65) 32.69,49.53 C120.1 C116.1
  BOTTOM w0.508: v2(68.07,26.54) v2(68.83,26.54) 69.6,26.54 72.14,29.08 72.14,34.16 69.9,36.4 ; R208.2 27.99,22.42 v1(30.26,22.42)
VBREF: length 2.9
  BOTTOM w0.381: C267.1 57.66,5.46 57.66,5.18 57.06,4.58 J17.9
VCAN: length 18.8
  TOP w0.584: J6.1 6.75,47.5 4.04,44.79 J9.9
VCAN0: length 42.3
  TOP w0.381: 18.99,45.28 21.08,47.37 J6.2 ; J10.2 20.26,38.54
  TOP w0.508: C24.1 v1(22.35,58.42)
  TOP w0.635: U16.8 v2(5.84,37.47)
  TOP w0.889: 21.65,37.15 J10.2 21.65,38.29
  LYR3 w0.381: v1(23.37,53.34) 21.08,51.05 J6.2
  LYR4 w0.381: v1(18.8,58.42) 19.58,59.21 21.56,59.21 v1(22.35,58.42) 22.35,56.13 23.37,55.12 v1(23.37,53.34)
  BOTTOM w0.381: v1(22.35,58.42) 22.73,58.42 ; 22.73,58.42 23.48,58.42 23.65,58.59 23.66,58.59 24,58.93 U27.8 ; 22.73,58.42 U27.7 ; C107.1 23.11,52.34 23.11,53.09 v1(23.37,53.34) ; R152.2 v1(18.8,58.42) ; v1(18.8,58.42) C98.1 ; v1(18.8,58.42) 17.65,58.42 17.14,58.93 U28.16
  BOTTOM w0.584: C191.1 9.53,37.58 9.53,38.61 C185.1
  BOTTOM w0.635: C191.1 6.1,37.21 v2(5.84,37.47)
VCOMH: length 10.7
  TOP w0.635: C63.1 66.42,7.87 63.94,5.4 63.94,3.38 63.33,2.77 63.22,2.77 v2(62.99,2.54)
  BOTTOM w0.254: J17.2 60.56,2.9 60.92,2.54 v2(62.99,2.54)
VDAC: length 25.1
  TOP w0.305: U14.E14 v1(35.37,40.45) ; U14.E6 v1(41.77,41.25) ; U14.N6 v1(41.77,46.85) ; v1(36.17,45.25) U14.K13 ; v1(35.37,48.45) U14.P14 ; v1(40.17,41.25) U14.F9 ; v1(40.17,48.45) U14.P9
  TOP w0.381: v2(11.43,18.59) R77.2
  LYR3 w0.381: v1(19.83,25.32) 19.41,24.91 19.29,24.91 v1(19.25,24.94) 19.22,24.91 18.12,24.91 17.78,25.25 14.5,25.25 13.06,23.8 11.76,23.8 10.72,22.76 10.72,20.37 10.83,20.26 10.86,20.26 11.38,19.74 11.38,19.71 11.43,19.66
  LYR4 w0.381: v1(35.37,48.45) 35.69,48.13
  BOTTOM w0.381: 33.15,39.12 33.15,37.19 32.88,36.92 32.88,36.18 31.5,34.8 31.34,34.8 ; 41.02,50.67 C152.1
  vias: v1(21.18,31.95) v2(12.14,18.59) v2(20.93,32.66)
VDIG1: length 3.4
  TOP w0.381: TP26.1 12.57,21.97 13.72,21.97 14.35,21.34 v1(14.48,21.34)
  BOTTOM w0.381: R218.1 v1(14.48,21.34)
VDIG2: length 76.3
  TOP w0.203: U14.E9 39.36,41.26 38.58,41.26 v1(38.57,41.25)
  TOP w0.305: U14.H15 v1(34.57,42.85) ; U14.E7 v1(41.77,40.45)
  TOP w0.381: U14.D10 U14.E9 ; U14.R10 38.97,48.86 38.96,48.86 v1(38.57,49.25) U14.R11 v1(37.77,48.45)
  LYR3 w0.381: v1(38.57,41.25) 39.12,40.7 40.45,40.7 40.73,40.98 41.24,40.98 v1(41.77,40.45) ; v1(32.97,47.65) 33.52,48.2 34.87,48.2 35.15,47.92 37.24,47.92 v1(37.77,48.45)
  LYR4 w0.381: 37.69,41.71 38.11,41.71 v1(38.57,41.25)
  LYR4 w0.508: v2(16.51,21.34) 16.51,21.49 v2(16.1,21.89) 16.1,23.06 16.51,23.47 16.51,28.47 15.48,29.5 15.37,29.5 15.02,29.86 15.02,29.97 15.01,29.97 15.01,30.48 15.14,30.61 15.14,36.03 17.02,37.91 17.02,47.94 21.57,52.49 23.9,52.49 23.99,52.58 28.11,52.58 28.63,52.06 30.1,52.06 32.97,49.19 v1(32.97,47.65) 32.97,43.48 33.4,43.06 33.4,43.06 33.6,42.85 v1(34.57,42.85)
  BOTTOM w0.305: C135.1 v1(37.77,48.45) ; v1(38.57,41.25) 39.08,40.74 C181.1 39.47,40.74 39.52,40.69 ; v1(34.57,42.85) 34.32,42.85 34.01,42.55 32.64,42.55 C166.1
  BOTTOM w0.508: R217.1 v2(16.51,21.34)
VMMC: length 128.8
  TOP w0.305: U14.H14 v1(35.37,43.65) U14.J14 ; U14.P11 v1(38.57,48.45) U14.P10
  TOP w0.381: U24.10 17.83,1.7 17.8,1.67 17.8,1.67 17.61,1.48 16.55,1.48 16.51,1.52 C68.1 13.27,1.52 v1(12.33,2.47)
  LYR3 w0.381: v1(38.57,48.45) 37.5,47.38 35.1,47.38 33.95,46.23 31.09,46.23 30.7,45.83 30.26,45.83 29.84,46.26 29.84,46.81 v2(29.46,47.18)
  LYR4 w0.508: 28.77,47.88 27.13,47.88 25.75,49.25 20.31,49.25 18.92,47.87 18.92,44.09 18.16,43.32 18.16,40.18 18.52,39.83 19.35,39.83 v2(19.91,39.27) 18.92,38.28 18.92,36.52 18.44,36.04 18.44,35.54 19.15,34.82 19.15,33.02 18.79,32.66 18.29,32.66 17.93,32.31 17.93,24.69 18.9,23.72 19.91,23.72 21.03,22.61 v2(21.03,21.89) 20.57,21.44 v2(20.57,21.34) 19.53,20.29 15.21,20.29 13.33,18.41 13.33,15.32 14.73,13.92 14.73,5.54 13.74,4.55 12.32,4.55 v2(11.43,3.66) 11.43,3.37 v1(12.33,2.47) 13.31,1.49 26.33,1.49 28.14,3.3 v1(32.51,3.3) 32.56,3.35 v1(32.56,4.01)
  BOTTOM w0.305: C160.2 35.37,42.96 v1(35.37,43.65) ; v1(38.57,48.45) 38.65,48.45 C119.2
  BOTTOM w0.381: R235.2 31.75,2.92 31.49,2.66 J16.4 ; R233.2 32.26,4.32 v1(32.56,4.01) ; R237.2 11.94,2.09 v1(12.33,2.47) 11.94,2.86 R236.2 11.94,3.15 v2(11.43,3.66) 11.94,4.17 R234.2
  BOTTOM w0.508: v1(32.51,3.3) R235.2 R233.2 R231.2 C272.1 31.75,7.38 C260.1
  BOTTOM w0.635: v2(20.76,39.24) 20.89,39.37 C179.2
  vias: v2(29.62,47.9)
VPLL: length 46.2
  TOP w0.381: FB2.2 38.38,27.47 38.58,27.47 40.21,25.84 41.13,25.84 41.67,25.31 41.67,22.34 41.55,22.23 v2(41.55,21.97)
  TOP w0.508: R76.2 9.91,18.64 10.49,19.23 v2(10.49,19.37)
  LYR3 w0.635: v2(10.49,19.37) 10.49,19.32 9.99,18.82 9.99,18.26 10.86,17.4 12.7,17.4 13.55,16.55 28.99,16.55 30.12,17.68 37.26,17.68 v2(41.55,21.97)
VPMIC_VRTC: length 8.7
  TOP w0.203: v1(16.89,5.59) 17.05,5.75 U22.29
  LYR3 w0.381: v1(13.03,6.31) 13.03,5.85 13.38,5.51 14.11,5.51 14.93,6.33 16.32,6.33 16.83,5.82 16.83,5.65 v1(16.89,5.59)
  BOTTOM w0.381: C261.1 R228.2 12.49,6.86 v1(13.03,6.31)
VPP: length 0.6
  TOP w0.305: U14.M5 v1(43.37,46.85)
VPROFI_DB: length 18.2
  TOP w0.584: J10.1 18.69,36.6 11.49,36.6 11.43,36.66 10.89,36.66 10.71,36.49 2.16,36.49
VPROFI_SRC: length 12.7
  TOP w0.381: v1(21.08,58.42) 21.91,59.25 23.05,59.25 23.5,59.69 D11.1 ; D13.1 v1(6.48,57.78)
  BOTTOM w0.381: v1(6.48,57.78) 5.86,57.78 C95.1 4.05,58.56 C96.1 ; 21.46,60.01 21.46,58.8 v1(21.08,58.42) 20.45,58.42 20.19,58.67 U27.5
VPROFI_TRANSA: length 4.4
  TOP w0.381: D13.2 5.46,61.09 5.52,61.03 L1.8
VPROFI_TRANSB: length 4.6
  TOP w0.381: D11.2 20,61.03 L1.5
VREFP_ADC: length 7.3
  TOP w0.203: 39.37,37.21 39.37,38.05
  TOP w0.305: 39.37,37.21 39.37,37.08 39,36.7 ; 39.37,38.05 U14.B9
  TOP w0.381: C34.1 C33.1 ; C34.1 38.35,34.8 R60.1 38.48,36.19 39,36.7 ; C34.1 C35.1
VRTC: length 44.5
  TOP w0.305: v1(41.77,39.65) U14.D7
  TOP w0.381: v1(41.63,36.03) 41.63,34.89 41.92,34.59 41.92,32.34 42.13,32.14 42.13,30.18 41.61,29.66 41.61,28.5 v1(41.68,28.43) 41.61,28.35 41.61,28.23 41.35,27.98 v1(41.31,27.98)
  LYR3 w0.305: v1(23.62,46.61) 23.37,46.86 23.37,48.39 23.11,48.64 v1(22.99,48.64)
  LYR4 w0.508: v1(23.62,46.61) 23.65,46.58 23.65,46.36 25.48,44.53 25.48,43.38 24.16,42.06 24.16,40.5 23.01,39.36 23.01,36.82 23.61,36.22 23.9,36.22 24.28,35.83 24.28,35.08 24.1,34.9 24.1,30.15 24.69,29.57 24.69,27.26 v2(24.7,27.25) 24.7,26.91 v2(24.99,26.62)
  BOTTOM w0.381: C125.1 23.79,48.6 23.61,48.6 23.58,48.64 v1(22.99,48.64) ; 35.05,26.29 35.1,26.34 36.14,26.34 36.63,26.82 37.38,26.82 37.87,26.33 39.85,26.33 41.31,27.8 41.31,27.97 v1(41.31,27.98) 41.31,27.98 41.35,28.02 41.35,28.08 41.4,28.13 41.4,28.23 41.6,28.43 v1(41.68,28.43) ; C197.1 41.7,36.03 v1(41.63,36.03)
VRTC_DET: length 2.2
  TOP w0.121: U13.3 24.63,46.35 v1(24.89,46.61)
  BOTTOM w0.121: R177.1 v1(24.89,46.61)
VRTC_DETB: length 4.8
  TOP w0.121: U13.2 24.14,44.2 v1(23.88,43.94) 23.63,44.18 U13.1
  BOTTOM w0.121: R177.2 C148.1 v1(23.88,43.94)
VTT_DDR: length 12.3
  BOTTOM w0.254: U29.3 68.33,33.02 68.2,32.9 68.2,32.54 68.19,32.52 68.19,32.42 68.15,32.37 68.15,32.21 67.94,32 ; 66.8,31.88 67.33,32.4 U29.5
  BOTTOM w0.381: R180.2 55.32,35.99 56.39,34.92 57.02,34.92
  vias: v2(57.74,33.91) v2(57.78,32.97) v2(57.78,30.77) v2(59,32.98) v2(59.1,33.92) v2(59.05,31.11) v2(60.33,31.11) v2(63.25,31.11)
XTIN: length 9.4
  TOP w0.121: U18.2 10.21,32.21 v1(10.16,32.26) 10.16,33.15 9.78,33.53 6.49,33.53 6.26,33.3 6.26,32.46 Y2.3
  BOTTOM w0.121: C211.2 v1(10.16,32.26)
XTOUT: length 9.3
  TOP w0.121: U18.3 10.37,31.71 v1(10.16,31.5) 10.16,31.19 9.6,30.63 9.6,28.87 Y2.1
  BOTTOM w0.121: C222.2 8.64,29.97 v1(10.16,31.5)
N16792759: length 9.2
  BOTTOM w0.121: U28.6 10.79,49.66 10.16,49.02 8,49.02 7.37,49.66 7.37,52.58 R174.2
N16818242: length 26.1
  TOP w0.121: v1(52.76,81.4) 52.87,81.29 U3.23 52.87,79.34 53.09,79.12 54.99,79.12 55.37,79.5 U3.18 55.37,81.66 54.86,82.16 54.86,83.19 C6.1 ; C16.1 51.26,69.39 v1(51.26,71.17) 51.31,71.17 51.49,70.99 52.07,70.99 52.37,71.29 U3.37
  BOTTOM w0.121: v1(52.76,81.4) 52.84,81.4 53.96,80.28 C81.1 ; C82.1 54.99,80.14 C81.1 ; C81.1 53.96,78.85 52.7,77.6 52.7,72.62 v1(51.26,71.17)
N16818333: length 3.2
  TOP w0.121: U3.20 54.37,82.92 R8.2
N16818596: length 4.3
  BOTTOM w0.121: J2.9 55.99,99.77 R89.1
N16819128: length 2.1
  TOP w0.121: R10.2 52.07,82.04 52.07,81.28 52.37,80.98 U3.24
N16839102: length 6.7
  BOTTOM w0.121: U35.14 51.32,11.55 49.98,10.21 49.98,8.91 C262.1 47.46,8.58 R227.1
N16839202: length 3
  TOP w0.121: R82.2 51.44,11.28 52.3,10.41 v1(52.69,10.41)
  BOTTOM w0.121: U35.13 v1(52.69,10.41)
N16839209: length 2.4
  BOTTOM w0.121: R223.2 59.84,10.05 U35.2
N16839216: length 2.3
  BOTTOM w0.121: R222.2 60.2,10.13 60.49,10.41 U35.1
N16844016: length 2.7
  TOP w0.121: D15.2 v1(76.35,84.85)
  BOTTOM w0.121: v1(76.35,84.85) R173.2
N16844076: length 2.7
  TOP w0.121: D14.2 v1(73.94,84.85)
  BOTTOM w0.121: v1(73.94,84.85) R155.2
N16844150: length 2.7
  TOP w0.121: D12.2 v1(71.52,84.85)
  BOTTOM w0.121: v1(71.52,84.85) R151.2
N16844168: length 2.7
  TOP w0.121: D10.2 v1(69.11,84.85)
  BOTTOM w0.121: v1(69.11,84.85) R143.2
N16844256: length 2.7
  TOP w0.121: D9.2 v1(76.35,80.54)
  BOTTOM w0.121: v1(76.35,80.54) R140.2
N16844274: length 2.7
  TOP w0.121: D8.2 v1(73.94,80.54)
  BOTTOM w0.121: v1(73.94,80.54) R136.2
N16844366: length 2.7
  TOP w0.121: D7.2 v1(71.52,80.54)
  BOTTOM w0.121: v1(71.52,80.54) R133.2
N16844384: length 2.7
  TOP w0.121: D6.2 v1(69.11,80.54)
  BOTTOM w0.121: v1(69.11,80.54) R132.2
N17075237: length 2.3
  TOP w0.121: D4.2 64.1,74.8 64.65,74.8 64.77,74.92 v1(64.77,75.56)
  BOTTOM w0.121: R130.1 v1(64.77,75.56)
N17107785: length 3
  TOP w0.121: U22.18 13.64,9.85 v1(13.59,9.91)
  BOTTOM w0.121: v1(13.59,9.91) 13.08,10.41 C254.1
N17123334: length 0.9
  TOP w0.203: U22.35 19.45,5.82
N17123833: length 0.9
  TOP w0.203: 21.46,9.65 21.26,9.45 U22.42
N19577113: length 7.9
  TOP w0.121: v1(14.05,6.22) 14.1,6.22 14.22,6.1 14.99,6.1 15.13,5.96 15.73,5.96 15.85,6.08 U22.26
  BOTTOM w0.121: v1(14.05,6.22) 13.83,6.22 13.29,5.68 12.77,5.68 12.74,5.72 12.19,5.72 11.66,6.24 10.02,6.24 R229.1
N19577116: length 8.1
  TOP w0.121: U22.19 13.9,9.45 v1(13.59,9.14)
  LYR3 w0.127: v1(9.3,8.06) 10.39,9.14 v1(13.59,9.14)
  BOTTOM w0.121: R228.1 10.41,6.86 9.41,7.86 9.41,7.95 v1(9.3,8.06)
N20350418: length 2.2
  TOP w0.121: R38.2 64.26,60.96 J5.3
N20364263: length 10.3
  TOP w0.121: v1(46.1,35.05) 46.1,34.86 46.68,34.28 46.68,34.27 48.68,32.27 48.68,31.78 48.77,31.69 TP23.1 ; v1(43.36,38.05) 43.36,38.86 U14.C5
  LYR3 w0.127: v1(43.36,38.05) 43.36,37.8 v1(46.1,35.05)
N21063525: length 5.1
  TOP w0.121: U1.F6 v1(23.57,88.63)
  BOTTOM w0.121: R101.1 26.42,91.48 v1(23.57,88.63)
N21210919: length 23.5
  BOTTOM w0.121: R225.1 R224.2 55.88,8.76 61.53,8.76 61.92,9.14 61.92,17.97 62.35,18.41 62.35,18.92 62.36,18.92 62.36,18.96 62.42,19.02 62.42,19.8 63.04,20.42 64.48,20.42 64.64,20.57 65.25,20.57 U34.4
N21210937: length 6.5
  TOP w0.381: L2.2 63.78,16.43 v2(62.99,15.64)
  BOTTOM w0.381: D20.2 63.25,15.08 62.99,15.33 v2(62.99,15.64) 62.99,15.75 62.74,16 62.74,17.19 63.27,17.73 U34.1
N21211001: length 14.7
  BOTTOM w0.121: U34.3 63.43,19.37 63.16,19.37 62.6,18.81 62.6,18.3 62.16,17.87 62.16,10.96 62.54,10.58 62.93,10.58 63.14,10.8 64.52,10.8 64.64,10.92 R221.2 R220.1 C255.2
N21251713: length 4.3
  BOTTOM w0.121: J2.11 61.48,99.77 R93.1
N21451174: length 2.4
  TOP w0.121: v1(31.14,30.35) 31.27,30.48 U17.3
  BOTTOM w0.121: v1(31.14,30.35) 30.99,30.2 R199.1
N21451189: length 3
  TOP w0.121: U17.7 25.96,29.21 26.02,29.25 26.98,29.25 27.61,29.88 v1(27.66,29.88)
  BOTTOM w0.121: R200.1 27.17,29.46 27.58,29.88 v1(27.66,29.88)
N21620210: length 13.6
  LYR3 w0.127: v1(67.44,9.4) 64.01,9.4 63.03,8.42 62.02,8.42 61.9,8.55 61.05,8.55 v1(59.19,10.41)
  BOTTOM w0.121: U35.3 v1(59.19,10.41) ; C259.1 66.42,8.38 v1(67.44,9.4) 67.56,9.4 68.34,8.62 R226.2
N21620213: length 13.8
  TOP w0.121: R84.2 67.56,10.3 67.56,10.35 67.6,10.39 v1(67.6,10.43)
  LYR3 w0.127: v1(67.6,10.43) 61.96,10.43 61.56,10.83 58.31,10.83 v1(57.89,10.41)
  BOTTOM w0.121: v1(67.6,10.43) 68.13,9.91 C256.1 ; U35.5 v1(57.89,10.41)
N21620216: length 14.8
  TOP w0.121: R83.2 67.56,11.3 v1(67.44,11.43)
  LYR3 w0.127: v1(56.59,10.41) 57.69,11.52 67.35,11.52 v1(67.44,11.43)
  BOTTOM w0.121: v1(67.44,11.43) 67.56,11.3 C253.1 ; U35.7 v1(56.59,10.41)
N21620219: length 16.6
  TOP w0.121: R81.2 v1(67.44,13.08)
  LYR3 w0.127: v1(67.44,13.08) 66.17,11.81 56.68,11.81 v1(55.29,10.41)
  BOTTOM w0.121: U35.9 v1(55.29,10.41) ; C250.1 v1(67.44,13.08)
N21620222: length 19.5
  TOP w0.121: v1(67.44,13.84) 67.44,13.84 67.44,14.61 67.68,14.86 R80.2
  LYR3 w0.127: v1(53.99,10.41) 55.64,12.07 60.33,12.07 62.1,13.84 v1(67.44,13.84)
  BOTTOM w0.121: C247.1 68.46,14.86 v1(67.44,13.84) ; U35.11 v1(53.99,10.41)
N21620225: length 19.8
  TOP w0.121: v1(67.44,15.75) 68.33,16.64 R79.2
  LYR3 w0.127: v1(67.44,15.75) 66.67,14.99 56.26,14.99 56.1,15.15 56.07,15.15 55.79,15.43 55.79,15.46 55.57,15.68 55.57,16.71 54.03,18.25 v1(54.03,18.27)
  BOTTOM w0.121: v1(54.03,18.27) 53.99,18.23 U35.18 ; v1(67.44,15.75) 68.33,16.64 C246.1
N21620228: length 18.9
  TOP w0.121: R74.2 68.34,18.53 67.94,18.92 v1(67.44,18.92)
  LYR3 w0.127: v1(55.24,18.41) 56.64,17.02 56.64,16.89 57.4,16.13 62.74,16.13 65.91,19.3 67.06,19.3 v1(67.44,18.92)
  BOTTOM w0.121: C241.1 67.56,18.92 v1(67.44,18.92) ; v1(55.24,18.41) 55.29,18.37 U35.20
N21620231: length 17
  TOP w0.121: R68.2 67.81,20.31 v1(67.44,19.94)
  LYR3 w0.127: v1(56.59,18.29) 58.36,16.51 62.36,16.51 62.93,17.08 62.93,17.21 65.66,19.94 v1(67.44,19.94)
  BOTTOM w0.121: v1(67.44,19.94) 67.69,19.68 68.2,19.68 C239.1 ; U35.22 v1(56.59,18.29)
N21797281: length 1.9
  TOP w0.121: U9.15 31.98,62.76 32,62.74 32,62.48 31.88,62.35 R40.2
N21797333: length 1.3
  TOP w0.121: R41.2 43.16,59.84 U11.15
N21800158: length 2.4
  BOTTOM w0.121: C162.1 56.39,42.55 R182.2 R179.2
N21868977: length 4.1
  BOTTOM w0.254: R195.2 C216.1 R191.1 69.98,31.96 69.33,32.61 U29.1
N21870936: length 3
  TOP w0.121: v1(66.04,42.8) 66.04,42.77 65.68,42.41 65.68,42.29 65.46,42.07 64.88,42.07 U15.L8
  BOTTOM w0.121: R183.2 v1(66.04,42.8)
N21881059: length 1.8
  TOP w0.121: D5.2 30.26,75.15 v1(30.61,74.8)
  BOTTOM w0.121: R131.1 30.73,74.93 v1(30.61,74.8)
N21881073: length 4.3
  BOTTOM w0.121: J1.11 41.16,99.77 R98.1
N21881115: length 4.3
  BOTTOM w0.121: J1.9 35.67,99.77 R94.1
N21881265: length 24.9
  TOP w0.121: C4.1 v1(38.61,82.42) 38.61,81.92 38.98,81.54 U2.18 ; U2.23 36.49,79.03 v1(36.32,78.87) ; C14.1 35.94,70.58 v1(35.96,70.6) 35.96,71.1 35.98,71.12 U2.37
  LYR4 w0.127: v1(35.96,70.6) 35.96,71.14 36.49,71.66 36.49,78.7 v1(36.32,78.87)
  BOTTOM w0.121: C84.1 35.8,78.34 v1(36.32,78.87) 36.2,78.99 36.2,80.81 37.81,82.42 v1(38.61,82.42) 38.61,81.85 38.64,81.82 38.66,81.82 38.99,81.49 C83.1
N21881353: length 3.2
  TOP w0.121: R7.2 37.98,82.92 U2.20
N21881950: length 2.1
  TOP w0.121: R9.2 35.98,81.74 U2.24
N22333314: length 9.4
  TOP w0.121: v1(22.91,98.89) 22.11,99.69 19.94,99.69 19.43,100.2 SW1.1
  BOTTOM w0.121: v1(22.91,98.89) U25.1 24.72,98.89 25.27,99.44 R88.2
N22333318: length 6.5
  TOP w0.121: v1(24.97,98.24) 25.27,98.54 25.27,100.46 24.51,101.22 SW1.2
  BOTTOM w0.121: R99.2 26.34,98.24 v1(24.97,98.24) U25.2
N22371955: length 2.1
  TOP w0.121: v1(64.16,27.73) 64.22,27.73 64.52,27.43 C43.1
  BOTTOM w0.121: U32.5 64.16,26.69 v1(64.16,27.73)
N23086594: length 2.3
  TOP w0.121: U3.25 50.45,78.82 49.94,79.33 49.49,79.33 R13.1
N23086888: length 1.9
  TOP w0.121: R12.1 32.68,78.82 U2.25
N27955689: length 3.1
  TOP w0.254: U18.59 15.77,35.58 v1(16,35.81)
  BOTTOM w0.381: R189.1 R188.2 v1(16,35.81)
N27956453: length 2
  TOP w0.121: v1(62.52,70.02) 63.04,69.49 U10.4
  BOTTOM w0.121: v1(62.52,70.02) 63.07,69.47 63.12,69.47
N28554546: length 6.5
  TOP w0.121: D1.2 76.08,96.39 75.48,96.99 71.08,96.99 R1.2
N28554548: length 2.2
  TOP w0.121: R2.2 71.06,95.55 71.38,95.55 71.66,95.84 D1.4
N28554589: length 8.9
  TOP w0.121: v1(68.74,96.18) 69.08,96.52 R1.1
  BOTTOM w0.121: Q2.3 72.68,93.37 72.42,93.62 70.96,93.62 70.73,93.86 68.57,93.86 68.32,94.11 68.32,94.66 68.11,94.87 68.11,95.55 v1(68.74,96.18)
N28554595: length 7.6
  TOP w0.121: v1(68.74,94.28) 69.04,93.98 R3.1
  BOTTOM w0.121: v1(68.74,94.28) 68.9,94.12 70.82,94.12 71.02,93.92 74.23,93.92 74.8,94.49 Q1.6
N28554605: length 4.4
  TOP w0.121: R2.1 70.29,95.8 71.03,95.8 v1(71.37,96.14)
  BOTTOM w0.121: Q1.3 73.1,96.14 v1(71.37,96.14)
N28554613: length 2.2
  TOP w0.121: R3.2 72.12,93.98 D1.3
N28559145: length 6.1
  TOP w0.121: D2.2 75.87,90.88 74.88,91.87 71.17,91.87 R4.2
N28559147: length 2.3
  TOP w0.121: D2.4 71.86,90.17 R5.2
N28559250: length 2.2
  TOP w0.121: D2.3 71.99,88.9 R6.2
N28559254: length 5.5
  TOP w0.121: v1(71.5,92.47) 70.5,92.47 69.6,91.57 R4.1
  BOTTOM w0.121: Q3.6 72.28,90.96 71.53,91.71 71.53,92.43 v1(71.5,92.47)
N28559256: length 6.4
  TOP w0.121: v1(74.07,91.45) 73.9,91.62 71.8,91.62 71.64,91.46 71.64,91.45 70.87,90.68 69.98,90.68 69.6,90.3 R5.1
  BOTTOM w0.121: Q2.6 74.69,92.07 v1(74.07,91.45)
N28559275: length 6.6
  TOP w0.121: R6.1 70.36,88.14 72.92,88.14 72.99,88.06 73.59,88.06 74.07,88.55 v1(74.07,89.04)
  BOTTOM w0.121: Q3.3 74.69,89.66 v1(74.07,89.04)
N28559577: length 2.8
  TOP w0.121: D3.1 v1(77.09,86.62)
  BOTTOM w0.121: Q4.6 76.56,86.09 v1(77.09,86.62)
N28559579: length 1.5
  TOP w0.121: D3.2 72.26,86.62 72.26,86.61
N28559581: length 3
  BOTTOM w0.121: Q4.2 72.3,86.74 R126.1 R127.2
N28629254: length 3.3
  TOP w0.121: D16.2 28.3,25.25 v1(28.75,24.81)
  BOTTOM w0.121: v1(28.75,24.81) 26.97,24.81 R208.1
